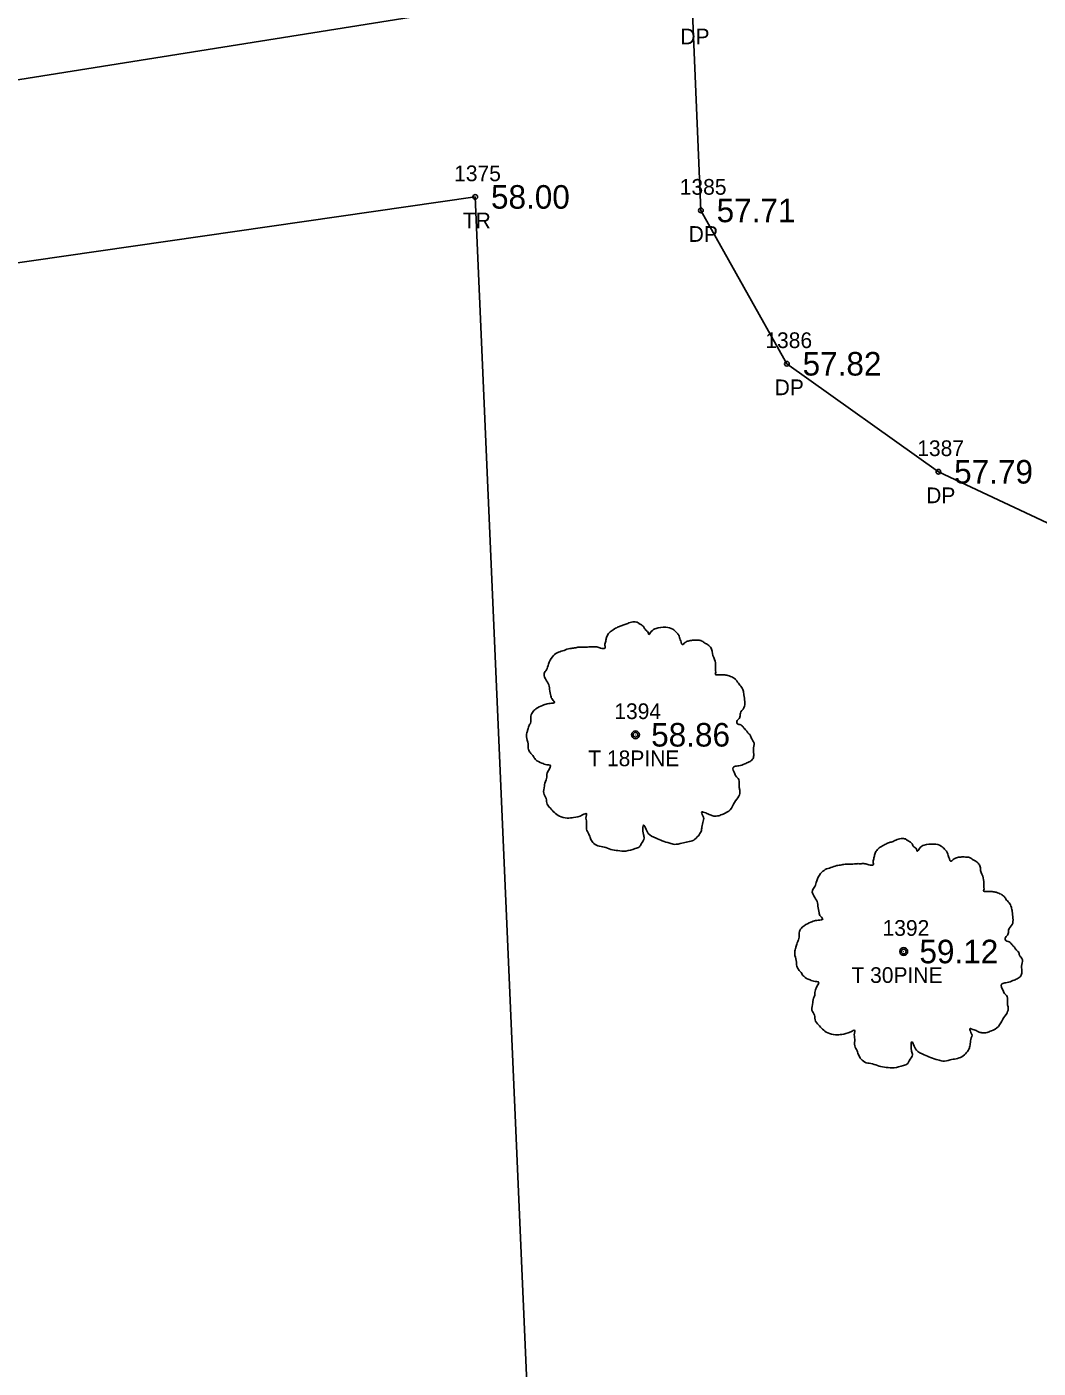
# Model space of a CAD drawing. Extents: x 2420113 to 2422887, y 845323 to 846653.
# Drawn here: x 2421383.1 to 2421447.4, y 845578.5 to 845663.9 of the extents above; entities that cross this region are included whole.
import ezdxf

# ---------------------------------------------------------------- set-up
doc = ezdxf.new("R2010")
doc.units = 0
for name, color, linetype in [('RD_EX_Driveway', 7, 'Continuous'), ('RD_EX_Driveway_txCode', 7, 'Continuous'), ('RD_EX_H2O', 7, 'Continuous'), ('RD_EX_TX_Driveway_ELEV', 7, 'Continuous'), ('RD_EX_TX_VEG_ELEV', 7, 'Continuous'), ('RD_EX_VEG', 7, 'Continuous'), ('RD_EX_VEG_txCode', 7, 'Continuous'), ('RD_SMD_Locator', 7, 'Continuous')]:
    doc.layers.add(name, color=color, linetype=linetype)

msp = doc.modelspace()

# ---------------------------------------------------------------- linework, layer by layer
at = {"layer": 'RD_EX_Driveway'}
msp.add_lwpolyline([(2421419.818, 845681.166), (2421427.875, 845673.766), (2421425.446, 845664.821), (2421425.975, 845652.245), (2421431.449, 845642.482), (2421441.096, 845635.605), (2421450.107, 845631.381), (2421470.335, 845586.723)], dxfattribs=at)
at = {"layer": 'RD_EX_H2O'}
msp.add_lwpolyline([(2420681.096, 845702.435), (2420748.921, 845698.406), (2420794.227, 845693.689), (2420899.447, 845684.247), (2421017.432, 845671.309), (2421111.865, 845660.393), (2421174.2, 845656.63), (2421235.056, 845654.383), (2421294.895, 845653.667), (2421353.19, 845655.886), (2421424.218, 845667.224)], dxfattribs=at)
at = {"layer": 'RD_EX_VEG'}
msp.add_lwpolyline([(2420391.438, 845659.631), (2420497.123, 845682.866), (2420554.964, 845697.51), (2420665.259, 845702.876), (2420735.635, 845697.654), (2420790.664, 845674.795), (2421018.223, 845655.053), (2421176.125, 845636.219), (2421296.761, 845636.574), (2421411.609, 845653.106), (2421415.242, 845569.551)], dxfattribs=at)
for centre, radius in [((2421421.808, 845618.86), 0.25), ((2421421.796, 845618.842), 0.0001), ((2421438.887, 845605.06), 0.25), ((2421438.874, 845605.041), 0.0001)]:
    msp.add_circle(centre, radius, dxfattribs=at)
for points in [[(2421421.94, 845626.028), (2421421.64, 845626.053), (2421421.315, 845625.953), (2421421.065, 845625.853), (2421420.841, 845625.778), (2421420.616, 845625.678), (2421420.316, 845625.503), (2421420.091, 845625.303), (2421419.966, 845625.053), (2421419.916, 845624.828), (2421419.866, 845624.553), (2421419.866, 845624.378), (2421419.741, 845624.353), (2421419.591, 845624.378), (2421419.341, 845624.453), (2421419.091, 845624.453), (2421418.841, 845624.453), (2421418.492, 845624.428), (2421418.142, 845624.428), (2421417.867, 845624.378), (2421417.542, 845624.328), (2421417.167, 845624.203), (2421416.817, 845624.078), (2421416.517, 845623.829), (2421416.268, 845623.354), (2421416.143, 845623.004), (2421415.993, 845622.754), (2421416.143, 845622.304), (2421416.318, 845621.954), (2421416.342, 845621.754), (2421416.417, 845621.33), (2421416.517, 845621.105), (2421416.642, 845620.905), (2421416.567, 845620.88), (2421416.193, 845620.83), (2421415.893, 845620.73), (2421415.468, 845620.505), (2421415.243, 845620.28), (2421415.143, 845619.955), (2421415.118, 845619.605), (2421415.018, 845619.406), (2421414.943, 845619.131), (2421414.918, 845619.056), (2421414.868, 845618.731), (2421414.968, 845618.281), (2421414.993, 845617.931), (2421415.118, 845617.706), (2421415.268, 845617.531), (2421415.443, 845617.281), (2421415.843, 845617.057), (2421416.168, 845616.957), (2421416.367, 845616.932), (2421416.193, 845616.432), (2421416.143, 845616.082), (2421416.018, 845615.682), (2421416.018, 845615.607), (2421415.968, 845615.132), (2421416.118, 845614.807), (2421416.193, 845614.433), (2421416.367, 845614.208), (2421416.642, 845613.908), (2421416.967, 845613.683), (2421417.467, 845613.558), (2421417.867, 845613.583), (2421418.442, 845613.758), (2421418.691, 845613.833), (2421418.666, 845613.658), (2421418.691, 845613.283), (2421418.691, 845612.858), (2421418.841, 845612.534), (2421418.941, 845612.259), (2421419.091, 845612.009), (2421419.416, 845611.784), (2421419.816, 845611.709), (2421420.241, 845611.559), (2421420.691, 845611.484), (2421421.19, 845611.459), (2421421.79, 845611.609), (2421422.065, 845611.734), (2421422.165, 845611.909), (2421422.365, 845612.284), (2421422.315, 845612.509), (2421422.34, 845613.108), (2421422.44, 845612.933), (2421422.615, 845612.583), (2421423.115, 845612.284), (2421423.514, 845612.109), (2421423.989, 845611.959), (2421424.289, 845611.884), (2421424.764, 845611.959), (2421425.139, 845612.034), (2421425.513, 845612.159), (2421425.813, 845612.434), (2421425.988, 845612.708), (2421426.038, 845612.983), (2421426.113, 845613.358), (2421426.163, 845613.533)], [(2421426.163, 845613.533), (2421426.088, 845613.708), (2421426.038, 845613.958), (2421426.113, 845613.933), (2421426.288, 845613.883), (2421426.563, 845613.758), (2421426.788, 845613.683), (2421427.113, 845613.708), (2421427.388, 845613.808), (2421427.837, 845614.083), (2421428.112, 845614.558), (2421428.387, 845614.957), (2421428.462, 845615.282), (2421428.412, 845615.507), (2421428.387, 845616.007), (2421428.187, 845616.257), (2421428.137, 845616.382), (2421428.037, 845616.782), (2421428.112, 845616.832), (2421428.387, 845616.882), (2421428.762, 845617.007), (2421429.037, 845617.131), (2421429.262, 845617.306), (2421429.337, 845617.531), (2421429.312, 845617.931), (2421429.362, 845618.331), (2421429.287, 845618.481), (2421429.187, 845618.631), (2421429.112, 845618.831), (2421428.962, 845618.981), (2421428.862, 845619.131), (2421428.762, 845619.231), (2421428.637, 845619.381), (2421428.462, 845619.505), (2421428.312, 845619.555), (2421428.262, 845619.705), (2421428.412, 845619.905), (2421428.462, 845620.005), (2421428.487, 845620.23), (2421428.712, 845620.58), (2421428.762, 845620.98), (2421428.712, 845621.405), (2421428.662, 845621.68), (2421428.512, 845621.954), (2421428.312, 845622.204), (2421428.187, 845622.379), (2421428.012, 845622.504), (2421427.688, 845622.629), (2421427.438, 845622.679), (2421427.088, 845622.679), (2421426.888, 845622.729), (2421426.913, 845622.779), (2421426.913, 845622.929), (2421426.913, 845623.204), (2421426.838, 845623.654), (2421426.688, 845624.153), (2421426.688, 845624.178), (2421426.588, 845624.428), (2421426.363, 845624.628), (2421426.188, 845624.728), (2421425.988, 845624.853), (2421425.738, 845624.878), (2421425.439, 845624.878), (2421425.164, 845624.828), (2421424.964, 845624.728), (2421424.789, 845624.603), (2421424.714, 845624.753), (2421424.614, 845625.053), (2421424.564, 845625.203), (2421424.414, 845625.378), (2421424.189, 845625.578), (2421423.739, 845625.703), (2421423.115, 845625.628), (2421422.815, 845625.428), (2421422.665, 845625.253), (2421422.615, 845625.378), (2421422.415, 845625.578), (2421422.315, 845625.753), (2421422.14, 845625.878), (2421421.99, 845625.978), (2421421.89, 845626.028)], [(2421439.019, 845612.227), (2421438.719, 845612.252), (2421438.394, 845612.152), (2421438.144, 845612.052), (2421437.919, 845611.977), (2421437.694, 845611.877), (2421437.394, 845611.702), (2421437.169, 845611.502), (2421437.044, 845611.252), (2421436.994, 845611.028), (2421436.945, 845610.753), (2421436.945, 845610.578), (2421436.82, 845610.553), (2421436.67, 845610.578), (2421436.42, 845610.653), (2421436.17, 845610.653), (2421435.92, 845610.653), (2421435.57, 845610.628), (2421435.22, 845610.628), (2421434.945, 845610.578), (2421434.621, 845610.528), (2421434.246, 845610.403), (2421433.896, 845610.278), (2421433.596, 845610.028), (2421433.346, 845609.553), (2421433.221, 845609.203), (2421433.071, 845608.953), (2421433.221, 845608.504), (2421433.396, 845608.154), (2421433.421, 845607.954), (2421433.496, 845607.529), (2421433.596, 845607.304), (2421433.721, 845607.104), (2421433.646, 845607.079), (2421433.271, 845607.029), (2421432.971, 845606.929), (2421432.546, 845606.704), (2421432.322, 845606.48), (2421432.222, 845606.155), (2421432.197, 845605.805), (2421432.097, 845605.605), (2421432.022, 845605.33), (2421431.997, 845605.255), (2421431.947, 845604.93), (2421432.047, 845604.48), (2421432.072, 845604.131), (2421432.197, 845603.906), (2421432.347, 845603.731), (2421432.521, 845603.481), (2421432.921, 845603.256), (2421433.246, 845603.156), (2421433.446, 845603.131), (2421433.271, 845602.631), (2421433.221, 845602.281), (2421433.096, 845601.882), (2421433.096, 845601.807), (2421433.046, 845601.332), (2421433.196, 845601.007), (2421433.271, 845600.632), (2421433.446, 845600.407), (2421433.721, 845600.107), (2421434.046, 845599.882), (2421434.546, 845599.757), (2421434.945, 845599.782), (2421435.52, 845599.957), (2421435.77, 845600.032), (2421435.745, 845599.857), (2421435.77, 845599.483), (2421435.77, 845599.058), (2421435.92, 845598.733), (2421436.02, 845598.458), (2421436.17, 845598.208), (2421436.495, 845597.983), (2421436.895, 845597.908), (2421437.319, 845597.758), (2421437.769, 845597.683), (2421438.269, 845597.658), (2421438.869, 845597.808), (2421439.144, 845597.933), (2421439.244, 845598.108), (2421439.443, 845598.483), (2421439.393, 845598.708), (2421439.418, 845599.308), (2421439.518, 845599.133), (2421439.693, 845598.783), (2421440.193, 845598.483), (2421440.593, 845598.308), (2421441.068, 845598.158), (2421441.368, 845598.083), (2421441.842, 845598.158), (2421442.217, 845598.233), (2421442.592, 845598.358), (2421442.892, 845598.633), (2421443.067, 845598.908), (2421443.117, 845599.183), (2421443.192, 845599.558), (2421443.242, 845599.732)], [(2421443.242, 845599.732), (2421443.167, 845599.907), (2421443.117, 845600.157), (2421443.192, 845600.132), (2421443.367, 845600.082), (2421443.642, 845599.957), (2421443.867, 845599.882), (2421444.191, 845599.907), (2421444.466, 845600.007), (2421444.916, 845600.282), (2421445.191, 845600.757), (2421445.466, 845601.157), (2421445.541, 845601.482), (2421445.491, 845601.707), (2421445.466, 845602.206), (2421445.266, 845602.456), (2421445.216, 845602.581), (2421445.116, 845602.981), (2421445.191, 845603.031), (2421445.466, 845603.081), (2421445.841, 845603.206), (2421446.116, 845603.331), (2421446.34, 845603.506), (2421446.415, 845603.731), (2421446.39, 845604.131), (2421446.44, 845604.53), (2421446.365, 845604.68), (2421446.265, 845604.83), (2421446.19, 845605.03), (2421446.041, 845605.18), (2421445.941, 845605.33), (2421445.841, 845605.43), (2421445.716, 845605.58), (2421445.541, 845605.705), (2421445.391, 845605.755), (2421445.341, 845605.905), (2421445.491, 845606.105), (2421445.541, 845606.205), (2421445.566, 845606.43), (2421445.791, 845606.779), (2421445.841, 845607.179), (2421445.791, 845607.604), (2421445.741, 845607.879), (2421445.591, 845608.154), (2421445.391, 845608.404), (2421445.266, 845608.579), (2421445.091, 845608.704), (2421444.766, 845608.829), (2421444.516, 845608.878), (2421444.166, 845608.878), (2421443.966, 845608.928), (2421443.991, 845608.978), (2421443.991, 845609.128), (2421443.991, 845609.403), (2421443.916, 845609.853), (2421443.767, 845610.353), (2421443.767, 845610.378), (2421443.667, 845610.628), (2421443.442, 845610.828), (2421443.267, 845610.928), (2421443.067, 845611.053), (2421442.817, 845611.078), (2421442.517, 845611.078), (2421442.242, 845611.028), (2421442.042, 845610.928), (2421441.867, 845610.803), (2421441.792, 845610.953), (2421441.692, 845611.252), (2421441.642, 845611.402), (2421441.493, 845611.577), (2421441.268, 845611.777), (2421440.818, 845611.902), (2421440.193, 845611.827), (2421439.893, 845611.627), (2421439.743, 845611.452), (2421439.693, 845611.577), (2421439.493, 845611.777), (2421439.393, 845611.952), (2421439.219, 845612.077), (2421439.069, 845612.177), (2421438.969, 845612.227)]]:
    msp.add_spline(points, degree=3, dxfattribs=at)
at = {"layer": 'RD_SMD_Locator'}
for centre in [(2421411.609, 845653.106), (2421425.975, 845652.245), (2421431.449, 845642.482), (2421441.096, 845635.605), (2421421.808, 845618.86), (2421438.887, 845605.06)]:
    msp.add_circle(centre, 0.15, dxfattribs=at)

# ---------------------------------------------------------------- texts
at = {"layer": 'RD_EX_Driveway_txCode'}
for s, p in [('DP', (2421424.667, 845662.821)), ('1385', (2421424.629, 845653.245)), ('DP', (2421425.196, 845650.245)), ('1386', (2421430.079, 845643.482)), ('DP', (2421430.67, 845640.482)), ('1387', (2421439.749, 845636.605)), ('DP', (2421440.316, 845633.605))]:
    msp.add_text(s, height=1, dxfattribs=at).set_placement(p)
at = {"layer": 'RD_EX_TX_Driveway_ELEV'}
for s, p in [('57.71', (2421426.975, 845651.495)), ('57.82', (2421432.449, 845641.732)), ('57.79', (2421442.096, 845634.855))]:
    msp.add_text(s, height=1.5, dxfattribs=at).set_placement(p)
at = {"layer": 'RD_EX_TX_VEG_ELEV'}
for s, p in [('58.00', (2421412.609, 845652.356)), ('58.86', (2421422.808, 845618.11)), ('59.12', (2421439.887, 845604.31))]:
    msp.add_text(s, height=1.5, dxfattribs=at).set_placement(p)
at = {"layer": 'RD_EX_VEG_txCode'}
for s, p in [('1375', (2421410.263, 845654.106)), ('TR', (2421410.814, 845651.106)), ('1394', (2421420.462, 845619.86)), ('T 18PINE', (2421418.804, 845616.86)), ('1392', (2421437.54, 845606.06)), ('T 30PINE', (2421435.56, 845603.06))]:
    msp.add_text(s, height=1, dxfattribs=at).set_placement(p)

doc.saveas('drawing.dxf')
